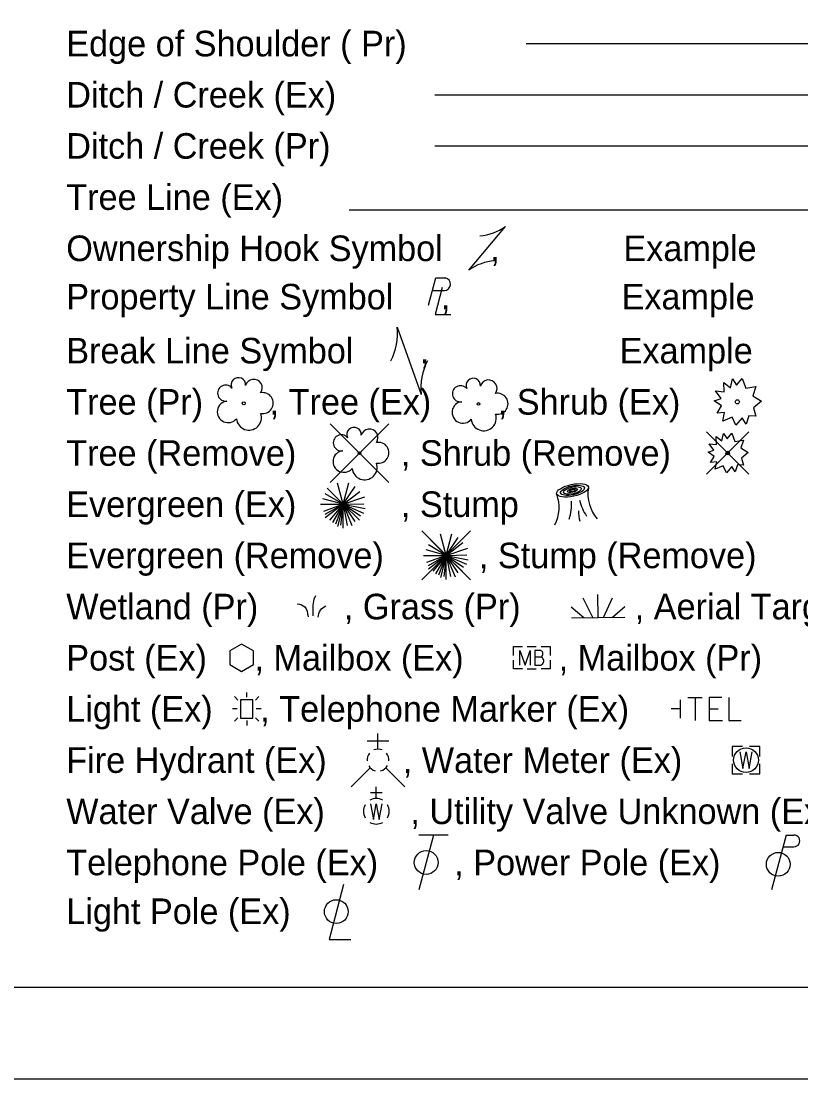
# Model space of a CAD drawing. Extents: x 0 to 34, y 0 to 22.
# Drawn here: x 7.93 to 12.19, y 0 to 5.79 of the extents above; entities that cross this region are included whole.
import ezdxf

# ---------------------------------------------------------------- set-up
doc = ezdxf.new("R2010")
doc.units = 0
for name, color, linetype in [('SH_Border', 7, 'Continuous'), ('SH_Cut_Line', 7, 'Continuous'), ('SH_Text', 7, 'Continuous')]:
    doc.layers.add(name, color=color, linetype=linetype)

msp = doc.modelspace()

# ---------------------------------------------------------------- linework, layer by layer
at = {"layer": 'SH_Border'}
msp.add_lwpolyline([(1.5, 21.5), (33.5, 21.5), (33.5, 0.5), (1.5, 0.5)], close=True, dxfattribs=at)
at = {"layer": 'SH_Cut_Line'}
msp.add_lwpolyline([(0, 0), (34, 0), (34, 22), (0, 22)], close=True, dxfattribs=at)
at = {"layer": 'SH_Text'}
for p, q in [((10.6907, 5.6637), (14.1741, 5.6637)), ((10.1904, 5.3837), (14.0904, 5.3837)), ((10.1904, 5.1037), (14.0904, 5.1037)), ((9.7227, 4.7537), (14.0727, 4.7537)), ((10.3777, 4.4237), (10.5777, 4.6637)), ((10.4777, 4.5437), (10.4777, 4.5437)), ((10.178, 4.3127), (10.2428, 4.3127)), ((10.2181, 4.2816), (10.2181, 4.2816)), ((9.9853, 4.1123), (10.1152, 3.7441)), ((10.0503, 3.9282), (10.0503, 3.9282)), ((9.6181, 3.5841), (9.9389, 3.2633)), ((9.9389, 3.5841), (9.6181, 3.2633)), ((11.6772, 3.5396), (11.9089, 3.3079)), ((11.9089, 3.5396), (11.6772, 3.3079)), ((9.7785, 3.4237), (9.7785, 3.4237)), ((11.7931, 3.4238), (11.7931, 3.4238)), ((9.689, 3.1435), (9.6581, 3.2589)), ((9.689, 3.1435), (9.7204, 3.261)), ((9.689, 3.1435), (9.7553, 3.2406)), ((9.689, 3.1435), (9.5913, 3.2009)), ((9.689, 3.1435), (9.6017, 3.2307)), ((9.689, 3.1435), (9.7804, 3.2136)), ((9.689, 3.1435), (9.8074, 3.1837)), ((9.5656, 3.1435), (9.689, 3.1435)), ((9.689, 3.1435), (9.5786, 3.1731)), ((9.689, 3.1435), (9.5817, 3.1045)), ((9.689, 3.1435), (9.5894, 3.0865)), ((9.689, 3.1435), (9.5913, 3.0686)), ((9.689, 3.1435), (9.6153, 3.0569)), ((9.689, 3.1435), (9.631, 3.0431)), ((9.689, 3.1435), (9.6473, 3.035)), ((9.689, 3.1435), (9.6574, 3.0221)), ((9.689, 3.1435), (9.6754, 3.0287)), ((9.689, 3.1435), (9.8017, 3.1458)), ((9.689, 3.0125), (9.689, 3.1435)), ((9.689, 3.1435), (9.712, 3.0276)), ((9.689, 3.1435), (9.7373, 3.0268)), ((9.689, 3.1435), (9.7524, 3.0487)), ((9.689, 3.1435), (9.7787, 3.0555)), ((9.689, 3.1435), (9.7845, 3.0796)), ((9.689, 3.1435), (9.8006, 3.095)), ((9.689, 3.1435), (9.8097, 3.1196)), ((10.9626, 3.1437), (10.9626, 3.1437)), ((10.1193, 2.9974), (10.3866, 2.7301)), ((10.3866, 2.9974), (10.1193, 2.7301)), ((10.253, 2.8637), (10.2221, 2.9791)), ((10.253, 2.8637), (10.2844, 2.9812)), ((10.253, 2.8637), (10.3193, 2.9609)), ((10.253, 2.8637), (10.1426, 2.8933)), ((10.253, 2.8637), (10.1553, 2.9212)), ((10.253, 2.8637), (10.1657, 2.9509)), ((10.253, 2.8637), (10.3444, 2.9339)), ((10.253, 2.8637), (10.3714, 2.9039)), ((10.1296, 2.8637), (10.253, 2.8637)), ((10.253, 2.8637), (10.1457, 2.8247)), ((10.253, 2.8637), (10.1534, 2.8067)), ((10.253, 2.8637), (10.1553, 2.7889)), ((10.253, 2.8637), (10.1793, 2.7771)), ((10.253, 2.8637), (10.195, 2.7634)), ((10.253, 2.8637), (10.2113, 2.7552)), ((10.253, 2.8637), (10.2214, 2.7423)), ((10.253, 2.8637), (10.2394, 2.749)), ((10.253, 2.8637), (10.3657, 2.866)), ((10.253, 2.7327), (10.253, 2.8637)), ((10.253, 2.8637), (10.276, 2.7478)), ((10.253, 2.8637), (10.3013, 2.747)), ((10.253, 2.8637), (10.3164, 2.7689)), ((10.253, 2.8637), (10.3427, 2.7757)), ((10.253, 2.8637), (10.3485, 2.7999)), ((10.253, 2.8637), (10.3646, 2.8152)), ((10.253, 2.8637), (10.3737, 2.8398)), ((10.253, 2.8637), (10.253, 2.8637)), ((11.0546, 2.5233), (11.0025, 2.6294)), ((11.0846, 2.5238), (11.0827, 2.6492)), ((11.1145, 2.5242), (11.1635, 2.6318)), ((11.0059, 2.5226), (10.9376, 2.5797)), ((11.1633, 2.5249), (11.2298, 2.584)), ((10.9384, 2.5216), (11.2307, 2.5259)), ((10.6957, 2.3648), (10.7458, 2.3648)), ((10.7213, 2.3037), (10.7213, 2.3037)), ((10.6957, 2.2427), (10.7458, 2.2427)), ((9.1134, 2.0722), (9.0949, 2.0909)), ((9.1617, 2.0877), (9.1617, 2.1143)), ((9.2283, 2.0909), (9.2097, 2.0722)), ((11.5343, 1.9737), (11.5343, 2.0737)), ((9.1095, 2.0241), (9.0829, 2.0241)), ((9.1134, 1.9753), (9.0949, 1.9566)), ((9.1617, 2.0237), (9.1617, 2.0237)), ((9.2283, 1.9566), (9.2097, 1.9753)), ((9.2404, 2.0241), (9.2137, 2.0241)), ((11.5343, 2.0237), (11.4846, 2.0237)), ((9.1617, 1.9597), (9.1617, 1.9332)), ((9.8797, 1.8039), (9.8797, 1.8899)), ((9.9397, 1.8469), (9.8197, 1.8469)), ((9.8798, 1.7437), (9.8798, 1.7437)), ((9.8798, 1.7437), (9.8798, 1.7437)), ((11.8933, 1.7437), (11.8933, 1.7437)), ((9.8374, 1.7013), (9.7334, 1.5974)), ((9.922, 1.7013), (10.026, 1.5974)), ((9.9024, 1.5656), (9.8388, 1.5656)), ((9.8706, 1.5337), (9.8706, 1.5973)), ((9.8706, 1.4637), (9.8706, 1.4637)), ((10.1837, 1.3337), (10.1033, 1.0337)), ((10.2637, 1.3337), (10.1037, 1.3337)), ((12.1126, 1.3337), (12.0323, 1.0337)), ((12.1126, 1.3337), (12.1551, 1.3337)), ((12.0956, 1.27), (12.1551, 1.27))]:
    msp.add_line(p, q, dxfattribs=at)
for points in [[(10.157, 4.2332), (10.1961, 4.3814), (10.2477, 4.3813)], [(10.2314, 4.3296), (10.1918, 4.1817), (10.2791, 4.1817)], [(11.8418, 3.7942), (11.8721, 3.831), (11.8928, 3.7783), (11.9474, 3.7873), (11.9305, 3.7367), (11.9777, 3.707), (11.9349, 3.6702), (11.9474, 3.6246), (11.9097, 3.628), (11.8935, 3.5823), (11.8721, 3.6169), (11.8381, 3.5761), (11.8167, 3.6204), (11.7657, 3.5989), (11.7753, 3.646), (11.7347, 3.6418), (11.7584, 3.6813), (11.72, 3.7097), (11.7569, 3.7229), (11.7266, 3.7631), (11.7731, 3.7576), (11.7716, 3.8095), (11.8093, 3.7811), (11.8196, 3.8303), (11.8418, 3.7942)], [(11.7895, 3.5007), (11.8152, 3.5319), (11.8328, 3.4871), (11.8792, 3.4948), (11.8648, 3.4518), (11.905, 3.4265), (11.8686, 3.3953), (11.8792, 3.3565), (11.8472, 3.3594), (11.8334, 3.3205), (11.8152, 3.3499), (11.7863, 3.3152), (11.7681, 3.3529), (11.7248, 3.3346), (11.7329, 3.3747), (11.6984, 3.3711), (11.7186, 3.4047), (11.6859, 3.4288), (11.7173, 3.44), (11.6915, 3.4742), (11.7311, 3.4695), (11.7298, 3.5136), (11.7618, 3.4895), (11.7706, 3.5313), (11.7895, 3.5007)], [(9.0685, 2.2662), (9.1334, 2.2287), (9.1983, 2.2662), (9.1983, 2.3412), (9.1334, 2.3787), (9.0685, 2.3412), (9.0685, 2.2662)], [(10.6213, 2.3163), (10.6213, 2.3648), (10.6698, 2.3648)], [(10.6565, 2.2637), (10.6565, 2.3437), (10.6855, 2.2637), (10.7132, 2.3437), (10.7132, 2.2637)], [(10.7724, 2.3072), (10.7756, 2.3104), (10.7774, 2.3123), (10.7787, 2.3141), (10.7793, 2.3154), (10.7806, 2.3179), (10.7812, 2.3198), (10.7825, 2.3242), (10.7825, 2.3261), (10.7825, 2.3286), (10.7818, 2.3324), (10.7806, 2.3356), (10.7787, 2.3381), (10.7756, 2.3406), (10.773, 2.3419), (10.7718, 2.3425), (10.7686, 2.3437), (10.7378, 2.3437), (10.7378, 2.2637), (10.7724, 2.2637), (10.7768, 2.2663), (10.7806, 2.2694), (10.7837, 2.2745), (10.7856, 2.2801), (10.7863, 2.2858), (10.7863, 2.2896), (10.785, 2.2934), (10.7825, 2.299), (10.7793, 2.3028), (10.7724, 2.3072), (10.7378, 2.3072)], [(10.7717, 2.3648), (10.8213, 2.3648), (10.8213, 2.3163)], [(10.6698, 2.2427), (10.6213, 2.2427), (10.6213, 2.2912)], [(10.8213, 2.2912), (10.8213, 2.2427), (10.7717, 2.2427)], [(11.5751, 2.0858), (11.6529, 2.0858)], [(11.6145, 2.0858), (11.6145, 1.9608)], [(11.7602, 2.0858), (11.6922, 2.0858), (11.6922, 1.9608), (11.7651, 1.9608)], [(11.7995, 2.0858), (11.7995, 1.9608), (11.8674, 1.9608)], [(11.6922, 2.0238), (11.7405, 2.0238)], [(11.8733, 1.8187), (11.8183, 1.8187), (11.8183, 1.7637)], [(11.9683, 1.7637), (11.9683, 1.8187), (11.9133, 1.8187)], [(11.86, 1.7887), (11.8767, 1.6987), (11.8933, 1.7887), (11.91, 1.6987), (11.9267, 1.7887)], [(11.8183, 1.7237), (11.8183, 1.6687), (11.8733, 1.6687)], [(11.9133, 1.6687), (11.9683, 1.6687), (11.9683, 1.7237)], [(9.8388, 1.5047), (9.8547, 1.4186), (9.8706, 1.5047), (9.8866, 1.4186), (9.9025, 1.5047)], [(9.6909, 1.0625), (9.6122, 0.7632), (9.7303, 0.7632)]]:
    msp.add_lwpolyline(points, dxfattribs=at)
msp.add_lwpolyline([(9.1283, 1.9737), (9.1949, 1.9737), (9.1949, 2.0737), (9.1283, 2.0737)], close=True, dxfattribs=at)
for centre, radius in [((9.1454, 3.6956), 0.0084), ((11.846, 3.7038), 0.0115), ((10.43, 3.6922), 0.0072), ((9.7785, 3.4237), 0.0072), ((11.793, 3.4238), 0.00979), ((11.8933, 1.7437), 0.0675), ((10.1435, 1.1837), 0.065), ((12.0698, 1.1737), 0.065), ((9.6516, 0.9148), 0.065)]:
    msp.add_circle(centre, radius, dxfattribs=at)
for centre, radius, start, end in [((10.4196, 4.8787), 0.2668, 273.69448, 306.33701), ((10.5358, 4.2088), 0.2668, 93.69448, 126.33701), ((10.2425, 4.3472), 0.0345, 270.47098, 81.3281), ((9.6533, 4.0798), 0.3335, 332.94224, 5.58476), ((10.4472, 3.7765), 0.3335, 152.94224, 185.58476), ((9.1159, 3.7967), 0.0395, 354.0047, 205.97412), ((9.2002, 3.7805), 0.0466, 323.82996, 165.0376), ((10.4005, 3.7932), 0.0395, 354.0047, 205.97412), ((10.4848, 3.7771), 0.0466, 323.82996, 165.0376), ((9.0462, 3.7516), 0.0441, 39.06254, 279.54124), ((10.3308, 3.7481), 0.0441, 39.06254, 279.54124), ((9.0598, 3.6492), 0.0592, 96.17219, 320.57371), ((9.2493, 3.6967), 0.0574, 259.14531, 101.45961), ((10.3444, 3.6457), 0.0592, 96.17219, 320.57371), ((10.5339, 3.6933), 0.0574, 259.14531, 101.45961), ((9.1738, 3.6175), 0.0685, 184.94757, 19.45715), ((10.4584, 3.614), 0.0685, 184.94757, 19.45715), ((9.7489, 3.5247), 0.0395, 354.0047, 205.97412), ((9.8332, 3.5086), 0.0466, 323.82996, 165.0376), ((9.6792, 3.4796), 0.0441, 39.06254, 279.54124), ((9.8823, 3.4248), 0.0574, 259.14531, 101.45961), ((9.6929, 3.3773), 0.0592, 96.17219, 320.57371), ((9.8068, 3.3456), 0.0685, 184.94757, 19.45715), ((10.671, 3.1264), 0.2001, 331.53375, 20.92689), ((11.2429, 3.2008), 0.2146, 171.41061, 219.91939), ((10.6867, 3.145), 0.2527, 340.79377, 3.54808), ((11.288, 3.2466), 0.316, 194.9653, 212.12159), ((11.1579, 3.1037), 0.1819, 178.79264, 197.12241), ((9.8798, 1.7437), 0.06, 68.13946, 112.03798), ((9.8798, 1.7437), 0.06, 140.02099, 184.06293), ((9.8798, 1.7437), 0.06, 356.01648, 39.98885), ((9.8798, 1.7437), 0.06, 211.87877, 255.84793), ((9.8798, 1.7437), 0.06, 283.82389, 329.90967), ((9.8706, 1.4638), 0.07, 60.01836, 120.01574), ((9.8706, 1.4638), 0.07, 150.01836, 209.98164), ((9.8706, 1.4638), 0.07, 330.01836, 29.98164), ((9.8706, 1.4638), 0.07, 239.98426, 299.98164), ((12.1558, 1.3019), 0.0319, 268.8767, 91.1233)]:
    msp.add_arc(centre, radius, start, end, dxfattribs=at)
for major_axis in [(0.0868, 0.0187), (0.0651, 0.0141), (0.0488, 0.0105), (0.0275, 0.0059), (0.0154, 0.0033)]:
    msp.add_ellipse((10.9439, 3.2193), major_axis=major_axis, ratio=0.36865, dxfattribs=at)
for points in [[(9.525, 2.5323), (9.525, 2.5796), (9.5309, 2.6241), (9.5398, 2.6448)], [(9.4377, 2.5993), (9.4791, 2.5816), (9.4969, 2.5283)], [(9.5528, 2.5251), (9.5646, 2.5636), (9.5941, 2.5873)]]:
    msp.add_spline(points, degree=3, dxfattribs=at)

# ---------------------------------------------------------------- texts
for s, p in [('Edge of Shoulder ( Pr)', (8.1741, 5.5937)), ('Ditch / Creek (Ex)', (8.1741, 5.3137)), ('Ditch / Creek (Pr)', (8.1741, 5.0337)), ('Tree Line (Ex)', (8.1741, 4.7537)), ('Ownership Hook Symbol     ,             Example', (8.1741, 4.4737)), ('Property Line Symbol     ,                  Example', (8.1741, 4.2091)), ('Break Line Symbol       ,                    Example', (8.1741, 3.9137)), ('Tree (Pr)       , Tree (Ex)       , Shrub (Ex)', (8.1741, 3.6337)), ('Tree (Remove)           , Shrub (Remove)', (8.1741, 3.3537)), ('Evergreen (Ex)           , Stump ', (8.1741, 3.0737)), ('Evergreen (Remove)          , Stump (Remove)', (8.1741, 2.7937)), ('Wetland (Pr)         , Grass (Pr)            , Aerial Target    ', (8.1741, 2.5137)), ('Post (Ex)     , Mailbox (Ex)          , Mailbox (Pr)', (8.1741, 2.2337)), ('Light (Ex)     , Telephone Marker (Ex)     ', (8.1741, 1.9537)), ('Fire Hydrant (Ex)        , Water Meter (Ex)', (8.1741, 1.6737)), ('Water Valve (Ex)         , Utility Valve Unknown (Ex.)', (8.1741, 1.3937)), ('Telephone Pole (Ex)        , Power Pole (Ex)', (8.1741, 1.1137)), ('Light Pole (Ex)     ', (8.1741, 0.8467))]:
    msp.add_text(s, height=0.14, dxfattribs=at).set_placement(p)

doc.saveas('drawing.dxf')
